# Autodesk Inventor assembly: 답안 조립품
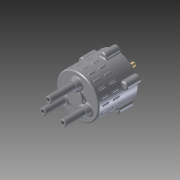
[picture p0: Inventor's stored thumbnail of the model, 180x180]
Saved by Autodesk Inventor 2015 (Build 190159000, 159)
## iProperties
Created: 2016-01
Part Number: 답안 조립품
Document SubType Name: Assembly
Designer: 601-23
Mass: 2168.28 g
Surface Area: 1791.59 cm^2
Volume: 441.32 cm^3
Density: 4.91317 g/cm^3
Author: 601-23
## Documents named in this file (14)
- C:\Users\601-23\Desktop\360106V1012\답안 조립품.iam
- C:\Users\601-23\Desktop\360106V1012\본체.ipt
- C:\Users\601-23\Desktop\360106V1012\슬라이드 축.ipt
- C:\Users\601-23\Desktop\360106V1012\커버.ipt
- C:\Users\601-23\Desktop\360106V1012\판캠.ipt
- C:\Users\601-23\Desktop\360106V1012\베어링 NA 4900.ipt
- C:\Users\601-23\Desktop\360106V1012\메인 축.ipt
- C:\Users\601-23\Desktop\360106V1012\멈춤링 22 x 1.2.ipt
- C:\Users\601-23\Desktop\360106V1012\오일실.ipt
- C:\Users\601-23\Desktop\360106V1012\멈춤링 10 x 1.ipt
- C:\Users\601-23\Desktop\360106V1012\스프링1.ipt
- C:\Users\601-23\Desktop\360106V1012\스프링2.ipt
- C:\Users\601-23\Desktop\360106V1012\스프링3.ipt
- C:\Users\601-23\Desktop\360106V1012\M5x0.8x20.ipt
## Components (5 placed, 1 different names)
1. M5x0.8x20:1
2. M5x0.8x20:2
3. M5x0.8x20:3
4. M5x0.8x20:4
5. M5x0.8x20:5 — 각도:2
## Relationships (1: Angle 1)
- 각도:2 [Angle]: M5x0.8x20:5
